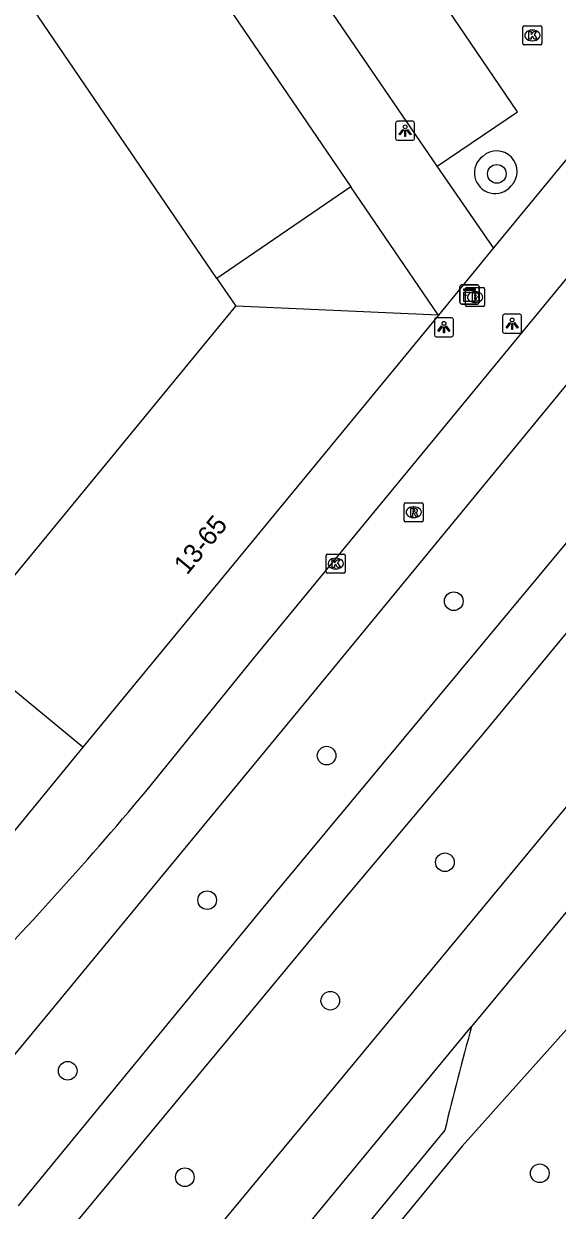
# Model space of a CAD drawing. Extents: x 155275 to 156263, y 382654 to 383635.
# Drawn here: x 155494.7 to 155522.6, y 382882.1 to 382944.3 of the extents above; entities that cross this region are included whole.
import ezdxf

# ---------------------------------------------------------------- set-up
doc = ezdxf.new("R2010")
doc.units = 0
for name, color, linetype in [('IMGEO_Boom', 7, 'Continuous'), ('IMGEO_Brandkraan', 7, 'Continuous'), ('IMGEO_Fietspad_gesloten', 7, 'Continuous'), ('IMGEO_Kast', 7, 'Continuous'), ('IMGEO_Kolk', 7, 'Continuous'), ('IMGEO_Lichtpunt', 7, 'Continuous'), ('IMGEO_Pand', 7, 'Continuous'), ('IMGEO_Pand_nummerreeks', 7, 'Continuous'), ('IMGEO_Pand_overbouw', 7, 'Continuous'), ('IMGEO_Rijbaan_lokaal_gesloten', 7, 'Continuous'), ('IMGEO_Rijbaan_lokaal_open', 7, 'Continuous'), ('IMGEO_Rioolput', 7, 'Continuous'), ('IMGEO_Voetpad_open', 7, 'Continuous')]:
    doc.layers.add(name, color=color, linetype=linetype)

msp = doc.modelspace()

# ---------------------------------------------------------------- linework, layer by layer
at = {"layer": 'IMGEO_Boom'}
for centre in [(155519.471, 382936.401), (155517.211, 382913.994), (155510.542, 382905.897), (155516.747, 382900.306), (155504.28, 382898.32), (155510.737, 382893.048), (155496.964, 382889.372), (155503.106, 382883.792), (155521.722, 382883.999)]:
    msp.add_circle(centre, 0.489, dxfattribs=at)
at = {"layer": 'IMGEO_Brandkraan'}
for p, q in [((155517.827, 382929.516), (155517.827, 382930.368)), ((155517.902, 382930.442), (155518.754, 382930.442)), ((155518.315, 382930.222), (155518.34, 382930.222)), ((155518.828, 382930.368), (155518.828, 382929.516)), ((155518.754, 382929.442), (155517.902, 382929.442)), ((155518.338, 382929.662), (155518.313, 382929.662))]:
    msp.add_line(p, q, dxfattribs=at)
for points in [[(155517.827, 382929.516), (155517.827, 382930.368)], [(155517.902, 382930.442), (155518.754, 382930.442)], [(155518.175, 382930.142), (155518.175, 382929.742), (155518.388, 382929.742)], [(155518.406, 382930.142), (155518.175, 382930.142)], [(155518.354, 382930.061), (155518.3, 382930.061), (155518.3, 382929.985)], [(155518.3, 382929.985), (155518.353, 382929.985)], [(155518.362, 382929.909), (155518.3, 382929.909), (155518.3, 382929.828)], [(155518.828, 382930.368), (155518.828, 382929.516)], [(155518.754, 382929.442), (155517.902, 382929.442)], [(155518.3, 382929.828), (155518.362, 382929.828)]]:
    msp.add_lwpolyline(points, dxfattribs=at)
for centre, radius, start, end in [((155517.904, 382930.366), 0.0765, 91.55205, 178.44795), ((155517.904, 382930.366), 0.0765, 91.55205, 178.44795), ((155518.355, 382930.023), 0.0379, 267.82845, 90.93552), ((155518.363, 382929.868), 0.0404, 269.87594, 90.50774), ((155518.41, 382929.997), 0.145, 59.4692, 91.53667), ((155518.435, 382930.044), 0.0922, 285.51372, 58.15012), ((155518.44, 382929.852), 0.105, 301.31148, 78.98903), ((155518.752, 382930.366), 0.0765, 1.55205, 88.44795), ((155518.752, 382930.366), 0.0765, 1.55205, 88.44795), ((155517.904, 382929.518), 0.0765, 181.55205, 268.44795), ((155517.904, 382929.518), 0.0765, 181.55205, 268.44795), ((155518.394, 382929.993), 0.251, 268.66757, 293.53466), ((155518.752, 382929.518), 0.0765, 271.55205, 358.44795), ((155518.752, 382929.518), 0.0765, 271.55205, 358.44795)]:
    msp.add_arc(centre, radius, start, end, dxfattribs=at)
for centre, major_axis, ratio, start_param, end_param in [((155518.314, 382929.942), (-0.387, 0.002), 0.722429, 4.712389, 7.853982), ((155518.339, 382929.942), (-0.39, 0.002), 0.717154, 1.570796, 4.712389)]:
    msp.add_ellipse(centre, major_axis=major_axis, ratio=ratio, start_param=start_param, end_param=end_param, dxfattribs=at)
at = {"layer": 'IMGEO_Fietspad_gesloten'}
for points in [[(155572.789, 382977.41), (155548.966, 382948.356), (155528.673, 382923.729), (155507.607, 382898.405), (155494.374, 382882.291)], [(155496.67, 382880.437), (155497.335, 382881.332), (155511.334, 382898.215), (155518.802, 382907.088), (155545.301, 382939.168), (155575.161, 382975.555)]]:
    msp.add_lwpolyline(points, dxfattribs=at)
at = {"layer": 'IMGEO_Kast'}
for p, q in [((155517.612, 382930.576), (155518.453, 382930.576)), ((155518.453, 382930.576), (155517.612, 382930.576)), ((155517.537, 382929.651), (155517.537, 382930.492)), ((155517.537, 382930.492), (155517.537, 382929.651)), ((155518.537, 382930.501), (155518.537, 382929.66)), ((155518.537, 382929.66), (155518.537, 382930.501)), ((155518.462, 382929.576), (155517.621, 382929.576)), ((155517.621, 382929.576), (155518.462, 382929.576))]:
    msp.add_line(p, q, dxfattribs=at)
for points in [[(155517.732, 382930.366), (155518.332, 382930.366), (155518.332, 382930.281), (155517.732, 382930.281), (155517.732, 382930.366)], [(155517.732, 382930.191), (155518.332, 382930.191), (155518.332, 382929.702), (155517.732, 382929.702), (155517.732, 382930.191)]]:
    msp.add_lwpolyline(points, dxfattribs=at)
msp.add_circle((155517.816, 382930.04), 0.0377, dxfattribs=at)
for centre, start, end in [((155517.615, 382930.498), 92.4484, 184.28452), ((155517.615, 382930.498), 92.4484, 184.28452), ((155518.459, 382930.498), 2.4484, 94.28452), ((155518.459, 382930.498), 2.4484, 94.28452), ((155517.615, 382929.654), 182.4484, 274.28452), ((155517.615, 382929.654), 182.4484, 274.28452), ((155518.459, 382929.654), 272.4484, 4.28452), ((155518.459, 382929.654), 272.4484, 4.28452)]:
    msp.add_arc(centre, 0.0779, start, end, dxfattribs=at)
at = {"layer": 'IMGEO_Kolk'}
for p, q in [((155520.832, 382943.233), (155520.832, 382944.085)), ((155520.907, 382944.159), (155521.759, 382944.159)), ((155521.32, 382943.939), (155521.345, 382943.939)), ((155521.833, 382944.085), (155521.833, 382943.233)), ((155521.759, 382943.159), (155520.907, 382943.159)), ((155521.343, 382943.379), (155521.318, 382943.379)), ((155510.52, 382915.539), (155510.52, 382916.391)), ((155510.595, 382916.465), (155511.447, 382916.465)), ((155511.008, 382916.245), (155511.033, 382916.245)), ((155511.521, 382916.391), (155511.521, 382915.539)), ((155511.031, 382915.685), (155511.006, 382915.685)), ((155511.447, 382915.465), (155510.595, 382915.465))]:
    msp.add_line(p, q, dxfattribs=at)
for points in [[(155520.832, 382943.233), (155520.832, 382944.085)], [(155520.907, 382944.159), (155521.759, 382944.159)], [(155521.153, 382943.859), (155521.276, 382943.859), (155521.276, 382943.708), (155521.406, 382943.859), (155521.57, 382943.859), (155521.424, 382943.708), (155521.577, 382943.459), (155521.425, 382943.459), (155521.34, 382943.623), (155521.276, 382943.556), (155521.276, 382943.459), (155521.153, 382943.459), (155521.153, 382943.859)], [(155521.833, 382944.085), (155521.833, 382943.233)], [(155521.759, 382943.159), (155520.907, 382943.159)], [(155510.52, 382915.539), (155510.52, 382916.391)], [(155510.595, 382916.465), (155511.447, 382916.465)], [(155511.521, 382916.391), (155511.521, 382915.539)], [(155510.841, 382916.165), (155510.964, 382916.165), (155510.964, 382916.014), (155511.094, 382916.165), (155511.258, 382916.165), (155511.112, 382916.014), (155511.265, 382915.765), (155511.113, 382915.765), (155511.028, 382915.929), (155510.964, 382915.862), (155510.964, 382915.765), (155510.841, 382915.765), (155510.841, 382916.165)], [(155511.447, 382915.465), (155510.595, 382915.465)]]:
    msp.add_lwpolyline(points, dxfattribs=at)
for centre, start, end in [((155520.909, 382944.083), 91.55205, 178.44795), ((155520.909, 382944.083), 91.55205, 178.44795), ((155521.757, 382944.083), 1.55205, 88.44795), ((155521.757, 382944.083), 1.55205, 88.44795), ((155520.909, 382943.235), 181.55205, 268.44795), ((155520.909, 382943.235), 181.55205, 268.44795), ((155521.757, 382943.235), 271.55205, 358.44795), ((155521.757, 382943.235), 271.55205, 358.44795), ((155510.597, 382916.389), 91.55205, 178.44795), ((155510.597, 382916.389), 91.55205, 178.44795), ((155511.445, 382916.389), 1.55205, 88.44795), ((155511.445, 382916.389), 1.55205, 88.44795), ((155510.597, 382915.541), 181.55205, 268.44795), ((155510.597, 382915.541), 181.55205, 268.44795), ((155511.445, 382915.541), 271.55205, 358.44795), ((155511.445, 382915.541), 271.55205, 358.44795)]:
    msp.add_arc(centre, 0.0765, start, end, dxfattribs=at)
for centre, major_axis, ratio, start_param, end_param in [((155521.319, 382943.659), (-0.387, 0.002), 0.722429, 4.712389, 7.853982), ((155521.344, 382943.659), (-0.39, 0.002), 0.717154, 1.570796, 4.712389), ((155511.007, 382915.965), (-0.387, 0.002), 0.722429, 4.712389, 7.853982), ((155511.032, 382915.965), (-0.39, 0.002), 0.717154, 1.570796, 4.712389)]:
    msp.add_ellipse(centre, major_axis=major_axis, ratio=ratio, start_param=start_param, end_param=end_param, dxfattribs=at)
at = {"layer": 'IMGEO_Lichtpunt'}
for p, q in [((155514.164, 382939.068), (155514.164, 382938.261)), ((155514.164, 382939.068), (155514.164, 382938.261)), ((155515.066, 382939.163), (155514.258, 382939.163)), ((155515.066, 382939.163), (155514.258, 382939.163)), ((155515.16, 382938.261), (155515.16, 382939.068)), ((155515.16, 382938.261), (155515.16, 382939.068)), ((155514.258, 382938.167), (155515.066, 382938.167)), ((155514.258, 382938.167), (155515.066, 382938.167)), ((155516.197, 382928.765), (155516.197, 382927.958)), ((155516.197, 382928.765), (155516.197, 382927.958)), ((155517.099, 382928.86), (155516.291, 382928.86)), ((155517.099, 382928.86), (155516.291, 382928.86)), ((155517.193, 382927.958), (155517.193, 382928.765)), ((155517.193, 382927.958), (155517.193, 382928.765)), ((155519.773, 382928.942), (155519.773, 382928.135)), ((155519.773, 382928.942), (155519.773, 382928.135)), ((155520.675, 382929.037), (155519.867, 382929.037)), ((155520.675, 382929.037), (155519.867, 382929.037)), ((155520.769, 382928.135), (155520.769, 382928.942)), ((155520.769, 382928.135), (155520.769, 382928.942)), ((155516.291, 382927.864), (155517.099, 382927.864)), ((155516.291, 382927.864), (155517.099, 382927.864)), ((155519.867, 382928.041), (155520.675, 382928.041)), ((155519.867, 382928.041), (155520.675, 382928.041))]:
    msp.add_line(p, q, dxfattribs=at)
for points in [[(155514.538, 382938.732), (155514.577, 382938.704), (155514.389, 382938.442), (155514.351, 382938.469), (155514.538, 382938.732)], [(155514.64, 382938.684), (155514.687, 382938.684), (155514.687, 382938.362), (155514.64, 382938.362), (155514.64, 382938.684)], [(155514.75, 382938.704), (155514.788, 382938.731), (155514.975, 382938.469), (155514.936, 382938.441), (155514.75, 382938.704)], [(155516.571, 382928.429), (155516.61, 382928.401), (155516.422, 382928.139), (155516.384, 382928.166), (155516.571, 382928.429)], [(155516.673, 382928.381), (155516.72, 382928.381), (155516.72, 382928.059), (155516.673, 382928.059), (155516.673, 382928.381)], [(155516.783, 382928.401), (155516.821, 382928.428), (155517.008, 382928.166), (155516.969, 382928.138), (155516.783, 382928.401)], [(155520.147, 382928.606), (155520.186, 382928.578), (155519.998, 382928.316), (155519.96, 382928.343), (155520.147, 382928.606)], [(155520.249, 382928.558), (155520.296, 382928.558), (155520.296, 382928.236), (155520.249, 382928.236), (155520.249, 382928.558)], [(155520.359, 382928.578), (155520.397, 382928.605), (155520.584, 382928.343), (155520.545, 382928.315), (155520.359, 382928.578)]]:
    msp.add_lwpolyline(points, dxfattribs=at)
for centre in [(155514.663, 382938.866), (155520.272, 382928.74), (155516.696, 382928.563)]:
    msp.add_circle(centre, 0.0994, dxfattribs=at)
for centre, start, end in [((155514.258, 382939.068), 90, 180), ((155514.258, 382939.068), 90, 180), ((155515.066, 382939.068), 0, 90), ((155515.066, 382939.068), 0, 90), ((155514.258, 382938.261), 180, 270), ((155514.258, 382938.261), 180, 270), ((155515.066, 382938.261), 270, 0), ((155515.066, 382938.261), 270, 360), ((155516.291, 382928.765), 90, 180), ((155516.291, 382928.765), 90, 180), ((155517.099, 382928.765), 0, 90), ((155517.099, 382928.765), 0, 90), ((155519.867, 382928.942), 90, 180), ((155519.867, 382928.942), 90, 180), ((155520.675, 382928.942), 0, 90), ((155520.675, 382928.942), 0, 90), ((155519.867, 382928.135), 180, 270), ((155519.867, 382928.135), 180, 270), ((155520.675, 382928.135), 270, 0), ((155520.675, 382928.135), 270, 360), ((155516.291, 382927.958), 180, 270), ((155516.291, 382927.958), 180, 270), ((155517.099, 382927.958), 270, 0), ((155517.099, 382927.958), 270, 360)]:
    msp.add_arc(centre, 0.0946, start, end, dxfattribs=at)
at = {"layer": 'IMGEO_Pand'}
for points in [[(155493.818, 382947.008), (155500.853, 382951.806), (155511.816, 382935.729), (155504.79, 382930.919)], [(155504.79, 382930.919), (155493.818, 382947.008)], [(155497.755, 382906.335), (155491.194, 382911.739), (155505.778, 382929.47)], [(155505.778, 382929.47), (155505.793, 382929.487), (155516.393, 382929.017), (155516.414, 382928.987)], [(155516.414, 382928.987), (155497.755, 382906.335)]]:
    msp.add_lwpolyline(points, dxfattribs=at)
at = {"layer": 'IMGEO_Pand_overbouw'}
msp.add_lwpolyline([(155505.778, 382929.47), (155505.793, 382929.487), (155516.393, 382929.017), (155511.816, 382935.729), (155504.79, 382930.919)], close=True, dxfattribs=at)
at = {"layer": 'IMGEO_Rijbaan_lokaal_gesloten'}
for points in [[(155501.355, 382904.375), (155506.73, 382911.007), (155559.373, 382974.92)], [(155490.162, 382885.345), (155509.377, 382908.625), (155562.068, 382972.685)], [(155500.998, 382876.481), (155523.385, 382903.532), (155571.314, 382961.825)], [(155554.945, 382936.396), (155524.977, 382899.965), (155521.205, 382895.388), (155518.222, 382891.797), (155518.138, 382891.696)], [(155503.043, 382873.39), (155518.138, 382891.696)]]:
    msp.add_lwpolyline(points, dxfattribs=at)
msp.add_arc((155362.899, 383019.401), 180.003, 315.4978, 320.28114, dxfattribs=at)
at = {"layer": 'IMGEO_Rijbaan_lokaal_open'}
for points in [[(155542.339, 382960.486), (155519.289, 382932.53)], [(155516.342, 382936.813), (155520.558, 382939.645), (155513.542, 382949.975), (155509.296, 382947.12)], [(155519.289, 382932.53), (155516.342, 382936.813)]]:
    msp.add_lwpolyline(points, dxfattribs=at)
for centre, radius, start, end in [((155519.458, 382936.528), 1.076, 315.02394, 132.67926), ((155519.379, 382936.453), 1.084, 126.93266, 320.77054)]:
    msp.add_arc(centre, radius, start, end, dxfattribs=at)
at = {"layer": 'IMGEO_Rioolput'}
for p, q in [((155514.609, 382918.232), (155514.609, 382919.084)), ((155514.684, 382919.158), (155515.536, 382919.158)), ((155515.097, 382918.938), (155515.122, 382918.938)), ((155515.61, 382919.084), (155515.61, 382918.232)), ((155515.536, 382918.158), (155514.684, 382918.158)), ((155515.12, 382918.378), (155515.095, 382918.378))]:
    msp.add_line(p, q, dxfattribs=at)
for points in [[(155514.609, 382918.232), (155514.609, 382919.084)], [(155514.684, 382919.158), (155515.536, 382919.158)], [(155515.198, 382918.856), (155514.946, 382918.858), (155514.946, 382918.458)], [(155515.124, 382918.777), (155515.07, 382918.777), (155515.07, 382918.696)], [(155515.61, 382919.084), (155515.61, 382918.232)], [(155515.536, 382918.158), (155514.684, 382918.158)], [(155514.946, 382918.458), (155515.07, 382918.458), (155515.07, 382918.62), (155515.081, 382918.62)], [(155515.07, 382918.696), (155515.122, 382918.696)], [(155515.128, 382918.591), (155515.199, 382918.458), (155515.339, 382918.458), (155515.274, 382918.584)]]:
    msp.add_lwpolyline(points, dxfattribs=at)
for centre, radius, start, end in [((155514.686, 382919.082), 0.0765, 91.55205, 178.44795), ((155514.686, 382919.082), 0.0765, 91.55205, 178.44795), ((155515.13, 382918.681), 0.0964, 77.00612, 93.18647), ((155515.144, 382918.738), 0.0378, 276.66336, 79.67722), ((155515.197, 382918.746), 0.109, 350.36119, 89.41601), ((155515.195, 382918.746), 0.112, 277.58423, 350.98172), ((155515.534, 382919.082), 0.0765, 1.55205, 88.44795), ((155515.534, 382919.082), 0.0765, 1.55205, 88.44795), ((155514.686, 382918.234), 0.0765, 181.55205, 268.44795), ((155514.686, 382918.234), 0.0765, 181.55205, 268.44795), ((155515.08, 382918.567), 0.0533, 26.02933, 88.69889), ((155515.106, 382918.885), 0.19, 274.7715, 282.96867), ((155515.179, 382918.531), 0.108, 29.51342, 73.79051), ((155515.534, 382918.234), 0.0765, 271.55205, 358.44795), ((155515.534, 382918.234), 0.0765, 271.55205, 358.44795)]:
    msp.add_arc(centre, radius, start, end, dxfattribs=at)
for centre, major_axis, ratio, start_param, end_param in [((155515.096, 382918.658), (-0.387, 0.002), 0.722429, 4.712389, 7.853982), ((155515.121, 382918.658), (-0.39, 0.002), 0.717154, 1.570796, 4.712389)]:
    msp.add_ellipse(centre, major_axis=major_axis, ratio=ratio, start_param=start_param, end_param=end_param, dxfattribs=at)
at = {"layer": 'IMGEO_Voetpad_open'}
for points in [[(155516.342, 382936.813), (155509.296, 382947.12)], [(155519.289, 382932.53), (155516.414, 382928.987)], [(155504.79, 382930.919), (155505.778, 382929.47)], [(155497.755, 382906.335), (155493.084, 382900.658)], [(155523.867, 382892.372), (155517.653, 382885.419), (155504.528, 382869.442)], [(155516.736, 382886.257), (155507.173, 382874.652)]]:
    msp.add_lwpolyline(points, dxfattribs=at)
msp.add_arc((155926.326, 382783.578), 422.264, 165.16457, 165.9267, dxfattribs=at)

# ---------------------------------------------------------------- texts
at = {"layer": 'IMGEO_Pand_nummerreeks'}
msp.add_text('13-65', height=1, rotation=50.52342, dxfattribs=at).set_placement((155503.222, 382915.331))

doc.saveas('drawing.dxf')
